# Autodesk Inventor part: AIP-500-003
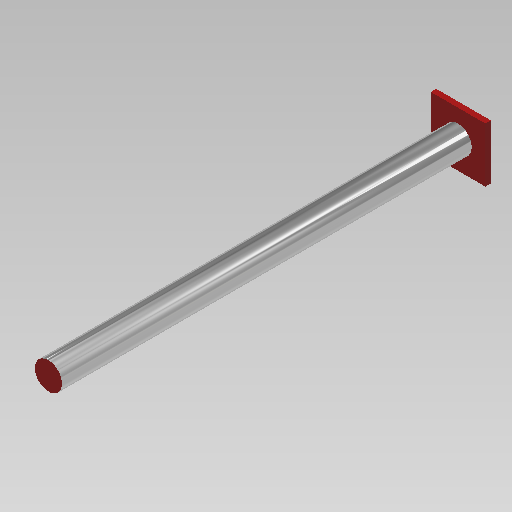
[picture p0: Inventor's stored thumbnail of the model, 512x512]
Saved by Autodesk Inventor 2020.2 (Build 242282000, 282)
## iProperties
Created: 2014-06
Part Number: AIP-500-003
Material: Ogólny
Document SubType Name: Modeling
Designer: F.Stasiak
Density: 1 g/cm^3
Appearance: Gładkie - czerwone
Catalog Web Link: www.expertbooks.pl
Manager: www.cadconsulting.pl
Company: Fabian Stasiak CAD Consulting
Author: F.Stasiak
Subject: Zbiór ćwiczeń. Autodesk Inventor 2020. Kurs Professional
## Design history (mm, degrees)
sketch "Szkic1"
  geometry: L1 (100, -100)-(-100, -100); L2 (-100, -100)-(-100, 100); L3 (-100, 100)-(100, 100); L4 (100, 100)-(100, -100); L5 (100, -100)-(-100, 100); L6 (-100, -100)-(100, 100); 1 further point
  constraints: 12 end point, 2 midpoint, 2 parallel, 1 horizontal, 1 perpendicular
  dimensions: "d1" = 200 distance of L2.end L3.end; "d2" = 200 distance of L1.end L2.end
extrude "Wyciągnięcie proste1" new body sketch "Szkic1" distance "d3" = 20; taper "d4" = 0 deg
sketch "Szkic2"
  geometry: C1 r 50 at (0, 0); 1 further point
  constraints: 1 centre point, 1 coincident
  dimensions: "d5" = 100 diameter of C1
extrude "Wyciągnięcie proste2" join sketch "Szkic2" distance "d6" = 1500; taper "d7" = 0 deg
node "Bryła1"
